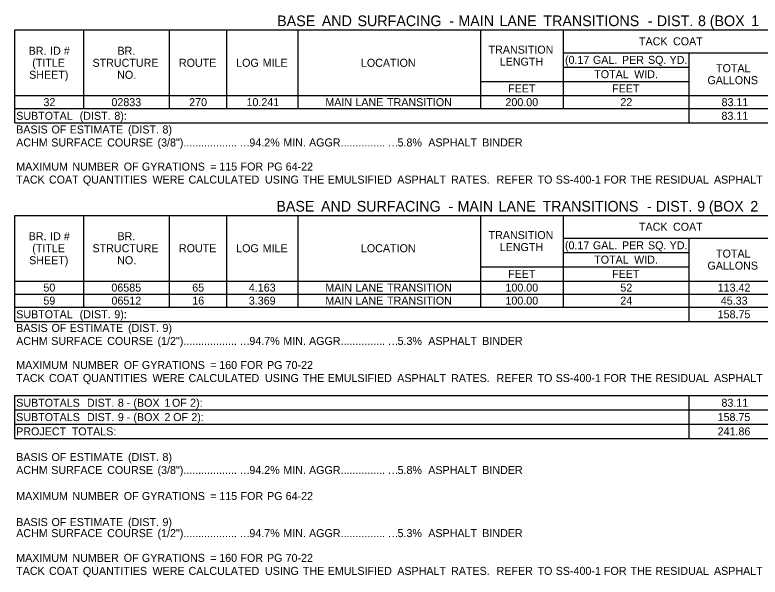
# Model space of a CAD drawing. Extents: x 544420 to 1930787, y -1947044 to 596640.
# Drawn here: x 546342 to 546901, y -1946896 to -1946475 of the extents above; entities that cross this region are included whole.
import ezdxf

# ---------------------------------------------------------------- set-up
doc = ezdxf.new("R2010")
doc.units = 0
doc.layers.add('Default', color=7, linetype='Continuous')

msp = doc.modelspace()

# ---------------------------------------------------------------- linework, layer by layer
at = {"layer": 'Default'}
for p, q in [((546342.21, -1946486.24), (547336.23, -1946486.24)), ((546342.21, -1946555.95), (546342.21, -1946486.24)), ((546342.21, -1946555.95), (546342.21, -1946486.24)), ((546393.89, -1946545.22), (546393.89, -1946486.24)), ((546458.24, -1946545.22), (546458.24, -1946486.24)), ((546501.14, -1946545.22), (546501.14, -1946486.24)), ((546554.76, -1946545.22), (546554.76, -1946486.24)), ((546691.75, -1946545.22), (546691.75, -1946486.24)), ((546753.66, -1946545.22), (546753.66, -1946486.24)), ((546753.66, -1946503.3), (546753.66, -1946486.24)), ((546753.66, -1946503.3), (547336.23, -1946503.3)), ((546847.75, -1946514.02), (546847.75, -1946503.3)), ((546847.75, -1946555.95), (546847.75, -1946503.3)), ((546753.66, -1946514.02), (546847.75, -1946514.02)), ((546691.75, -1946524.75), (546753.66, -1946524.75)), ((546691.75, -1946524.75), (546847.75, -1946524.75)), ((546847.75, -1946535.47), (546847.75, -1946524.75)), ((546342.21, -1946535.47), (546847.75, -1946535.47)), ((546342.21, -1946535.47), (547336.23, -1946535.47)), ((546847.75, -1946535.47), (546967.68, -1946535.47)), ((546342.21, -1946545.22), (547336.23, -1946545.22)), ((546342.21, -1946545.22), (547336.23, -1946545.22)), ((546342.21, -1946555.95), (547336.23, -1946555.95)), ((546342.21, -1946625.17), (547336.23, -1946625.17)), ((546342.21, -1946704.64), (546342.21, -1946625.17)), ((546342.21, -1946704.64), (546342.21, -1946625.17)), ((546393.89, -1946693.91), (546393.89, -1946625.17)), ((546458.24, -1946693.91), (546458.24, -1946625.17)), ((546501.14, -1946693.91), (546501.14, -1946625.17)), ((546554.76, -1946693.91), (546554.76, -1946625.17)), ((546691.75, -1946693.91), (546691.75, -1946625.17)), ((546753.66, -1946693.91), (546753.66, -1946625.17)), ((546753.66, -1946642.24), (546753.66, -1946625.17)), ((546753.66, -1946642.24), (547336.23, -1946642.24)), ((546847.75, -1946652.96), (546847.75, -1946642.24)), ((546847.75, -1946704.64), (546847.75, -1946642.24)), ((546753.66, -1946652.96), (546847.75, -1946652.96)), ((546691.75, -1946663.69), (546753.66, -1946663.69)), ((546691.75, -1946663.69), (546847.75, -1946663.69)), ((546847.75, -1946674.41), (546847.75, -1946663.69)), ((546342.21, -1946674.41), (547336.23, -1946674.41)), ((546847.75, -1946674.41), (546967.68, -1946674.41)), ((546342.21, -1946684.16), (547336.23, -1946684.16)), ((546342.21, -1946693.91), (547336.23, -1946693.91)), ((546342.21, -1946704.64), (547336.23, -1946704.64)), ((546342.21, -1946760.21), (546554.76, -1946760.21)), ((546342.21, -1946760.21), (547336.23, -1946760.21)), ((546342.21, -1946792.39), (546342.21, -1946760.21)), ((546342.21, -1946792.39), (546342.21, -1946760.21)), ((546554.76, -1946760.21), (547076.88, -1946760.21)), ((546847.75, -1946792.39), (546847.75, -1946760.21)), ((546342.21, -1946770.94), (547336.23, -1946770.94)), ((546342.21, -1946781.66), (547336.23, -1946781.66)), ((546342.21, -1946792.39), (547336.23, -1946792.39))]:
    msp.add_line(p, q, dxfattribs=at)

# ---------------------------------------------------------------- texts
for s, height, p in [('BASE', 8, (546538.89, -1946483.41)), (' AND', 8, (546569.4, -1946483.41)), (' SURFACING', 8, (546596.17, -1946483.41)), (' -', 8, (546665.04, -1946483.41)), (' MAIN', 8, (546671.79, -1946483.41)), (' LANE', 8, (546702.56, -1946483.41)), (' TRANSITIONS', 8, (546735.54, -1946483.41)), (' -', 8, (546813.86, -1946483.41)), (' DIST.', 8, (546820.61, -1946483.41)), (' 8', 8, (546851.51, -1946483.41)), (' (BOX', 8, (546860.33, -1946483.41)), (' 1', 8, (546891.36, -1946483.41)), ('TACK', 6, (546810.24, -1946497.77)), (' COAT', 6, (546833.52, -1946497.77)), ('BR.', 6, (546352.53, -1946504.85)), (' ID', 6, (546366.39, -1946504.85)), (' #', 6, (546376.68, -1946504.85)), ('BR.', 6, (546419.13, -1946504.85)), ('TRANSITION', 6, (546697.43, -1946503.99)), ('(TITLE', 6, (546355.22, -1946513.85)), ('STRUCTURE', 6, (546400.42, -1946513.85)), ('ROUTE', 6, (546465.22, -1946513.85)), ('LOG', 6, (546508.15, -1946513.85)), (' MILE', 6, (546525.81, -1946513.85)), ('LOCATION', 6, (546601.7, -1946513.85)), ('LENGTH', 6, (546705.8, -1946512.99)), ('(0.17', 6, (546754.73, -1946511.66)), (' GAL.', 6, (546773.46, -1946511.66)), (' PER', 6, (546795.24, -1946511.66)), (' SQ.', 6, (546814.76, -1946511.66)), (' YD.', 6, (546830.96, -1946511.66)), ('TOTAL', 6, (546868.03, -1946517.89)), ('SHEET)', 6, (546352.9, -1946522.85)), ('NO.', 6, (546418.9, -1946522.85)), ('TOTAL', 6, (546776.68, -1946522.39)), (' WID.', 6, (546804.37, -1946522.39)), ('GALLONS', 6, (546861.59, -1946526.89)), ('FEET', 6, (546712.08, -1946533.11)), ('FEET', 6, (546790.08, -1946533.11)), ('32', 6, (546363.61, -1946543.35)), ('02833', 6, (546414.6, -1946543.35)), ('270', 6, (546472.9, -1946543.35)), ('10.241', 6, (546515.91, -1946543.35)), ('MAIN', 6, (546575.02, -1946543.35)), (' LANE', 6, (546595.3, -1946543.35)), (' TRANSITION', 6, (546619.08, -1946543.35)), ('200.00', 6, (546710.09, -1946543.35)), ('22', 6, (546796.27, -1946543.35)), ('83.11', 6, (546872.16, -1946543.35)), (' (DIST.', 6, (546388.58, -1946553.59)), (' 8):', 6, (546414.55, -1946553.59)), ('SUBTOTAL', 6, (546343.19, -1946553.59)), ('83.11', 6, (546872.07, -1946553.59)), ('BASIS', 6, (546343.19, -1946563.82)), (' OF', 6, (546367.45, -1946563.82)), (' ESTIMATE', 6, (546381.04, -1946563.82)), (' (DIST.', 6, (546424.84, -1946563.82)), (' 8)', 6, (546450.65, -1946563.82)), ('ACHM', 6, (546343.19, -1946573.57)), (' SURFACE', 6, (546367.24, -1946573.57)), (' COURSE', 6, (546409.19, -1946573.57)), (' (3/8")..................', 6, (546446.94, -1946573.57)), ('94.2%', 6, (546518.04, -1946573.57)), (' MIN.', 6, (546541.28, -1946573.57)), (' AGGR...............', 6, (546560.57, -1946573.57)), ('5.8%', 6, (546629.17, -1946573.57)), ('  ASPHALT', 6, (546647.75, -1946573.57)), (' BINDER', 6, (546690.45, -1946573.57)), ('…', 6, (546510.64, -1946573.57)), ('…', 6, (546621.77, -1946573.57)), ('MAXIMUM', 6, (546343.19, -1946591.61)), (' NUMBER', 6, (546383.08, -1946591.61)), (' OF', 6, (546421.62, -1946591.61)), (' GYRATIONS', 6, (546435.21, -1946591.61)), (' 115', 6, (546493.23, -1946591.61)), (' FOR', 6, (546509.21, -1946591.61)), (' PG', 6, (546529.12, -1946591.61)), (' 64-22', 6, (546543.04, -1946591.61)), (' =', 6, (546486.48, -1946591.61)), ('TACK', 6, (546343.19, -1946601.36)), (' COAT', 6, (546365.53, -1946601.36)), (' QUANTITIES', 6, (546390.98, -1946601.36)), (' WERE', 6, (546443.18, -1946601.36)), (' CALCULATED', 6, (546470.21, -1946601.36)), (' USING', 6, (546527.53, -1946601.36)), (' THE', 6, (546555.89, -1946601.36)), (' EMULSIFIED', 6, (546574.54, -1946601.36)), (' ASPHALT', 6, (546626.73, -1946601.36)), (' RATES.', 6, (546667.09, -1946601.36)), ('  REFER', 6, (546698.97, -1946601.36)), (' TO', 6, (546731.93, -1946601.36)), (' SS-400-1', 6, (546745.53, -1946601.36)), (' FOR', 6, (546781.72, -1946601.36)), (' THE', 6, (546801.63, -1946601.36)), (' RESIDUAL', 6, (546820.28, -1946601.36)), (' ASPHALT', 6, (546864.24, -1946601.36)), ('BASE', 8, (546538.28, -1946622.35)), (' AND', 8, (546568.78, -1946622.35)), (' SURFACING', 8, (546595.55, -1946622.35)), (' MAIN', 8, (546671.17, -1946622.35)), (' LANE', 8, (546701.94, -1946622.35)), (' TRANSITIONS', 8, (546734.92, -1946622.35)), (' DIST.', 8, (546819.99, -1946622.35)), (' 9', 8, (546850.89, -1946622.35)), (' (BOX', 8, (546859.69, -1946622.35)), (' 2', 8, (546890.73, -1946622.35)), (' -', 8, (546664.43, -1946622.35)), (' -', 8, (546813.25, -1946622.35)), ('TACK', 6, (546810.24, -1946636.7)), (' COAT', 6, (546833.52, -1946636.7)), ('BR.', 6, (546352.53, -1946643.79)), (' ID', 6, (546366.39, -1946643.79)), (' #', 6, (546376.68, -1946643.79)), ('BR.', 6, (546419.13, -1946643.79)), ('TRANSITION', 6, (546697.43, -1946642.93)), ('(TITLE', 6, (546355.22, -1946652.79)), ('STRUCTURE', 6, (546400.42, -1946652.79)), ('ROUTE', 6, (546465.22, -1946652.79)), ('LOG', 6, (546508.15, -1946652.79)), (' MILE', 6, (546525.81, -1946652.79)), ('LOCATION', 6, (546601.7, -1946652.79)), ('LENGTH', 6, (546705.8, -1946651.93)), ('(0.17', 6, (546754.73, -1946650.6)), (' GAL.', 6, (546773.46, -1946650.6)), (' PER', 6, (546795.24, -1946650.6)), (' SQ.', 6, (546814.76, -1946650.6)), (' YD.', 6, (546830.96, -1946650.6)), ('TOTAL', 6, (546868.03, -1946656.82)), ('SHEET)', 6, (546352.9, -1946661.79)), ('NO.', 6, (546418.9, -1946661.79)), ('TOTAL', 6, (546776.68, -1946661.32)), (' WID.', 6, (546804.37, -1946661.32)), ('GALLONS', 6, (546861.59, -1946665.82)), ('FEET', 6, (546712.08, -1946672.05)), ('FEET', 6, (546790.08, -1946672.05)), ('50', 6, (546363.59, -1946682.29)), ('06585', 6, (546414.58, -1946682.29)), ('65', 6, (546475.2, -1946682.29)), ('4.163', 6, (546517.66, -1946682.29)), ('MAIN', 6, (546575.02, -1946682.29)), (' LANE', 6, (546595.3, -1946682.29)), (' TRANSITION', 6, (546619.08, -1946682.29)), ('100.00', 6, (546710.09, -1946682.29)), ('52', 6, (546796.27, -1946682.29)), ('113.42', 6, (546869.28, -1946682.29)), ('59', 6, (546363.58, -1946692.04)), ('06512', 6, (546414.64, -1946692.04)), ('16', 6, (546475.22, -1946692.04)), ('3.369', 6, (546517.65, -1946692.04)), ('MAIN', 6, (546575.02, -1946692.04)), (' LANE', 6, (546595.3, -1946692.04)), (' TRANSITION', 6, (546619.08, -1946692.04)), ('100.00', 6, (546710.09, -1946692.04)), ('24', 6, (546796.25, -1946692.04)), ('45.33', 6, (546871.58, -1946692.04)), ('SUBTOTAL', 6, (546343.19, -1946702.27)), (' (DIST.', 6, (546388.58, -1946702.27)), (' 9):', 6, (546414.55, -1946702.27)), ('158.75', 6, (546869.23, -1946702.27)), ('BASIS', 6, (546343.19, -1946712.51)), (' OF', 6, (546367.45, -1946712.51)), (' ESTIMATE', 6, (546381.04, -1946712.51)), (' (DIST.', 6, (546424.84, -1946712.51)), (' 9)', 6, (546450.65, -1946712.51)), ('ACHM', 6, (546343.19, -1946722.26)), (' SURFACE', 6, (546367.24, -1946722.26)), (' COURSE', 6, (546409.19, -1946722.26)), (' (1/2")..................', 6, (546446.94, -1946722.26)), ('94.7%', 6, (546518.04, -1946722.26)), (' MIN.', 6, (546541.28, -1946722.26)), (' AGGR...............', 6, (546560.57, -1946722.26)), ('5.3%', 6, (546629.17, -1946722.26)), ('  ASPHALT', 6, (546647.75, -1946722.26)), (' BINDER', 6, (546690.45, -1946722.26)), ('…', 6, (546510.64, -1946722.26)), ('…', 6, (546621.77, -1946722.26)), ('MAXIMUM', 6, (546343.19, -1946740.3)), (' NUMBER', 6, (546383.08, -1946740.3)), (' OF', 6, (546421.62, -1946740.3)), (' GYRATIONS', 6, (546435.21, -1946740.3)), (' =', 6, (546486.48, -1946740.3)), (' 160', 6, (546493.23, -1946740.3)), (' FOR', 6, (546509.14, -1946740.3)), (' PG', 6, (546529.05, -1946740.3)), (' 70-22', 6, (546542.97, -1946740.3)), ('TACK', 6, (546343.19, -1946750.05)), (' COAT', 6, (546365.53, -1946750.05)), (' QUANTITIES', 6, (546390.98, -1946750.05)), (' WERE', 6, (546443.18, -1946750.05)), (' CALCULATED', 6, (546470.21, -1946750.05)), (' USING', 6, (546527.53, -1946750.05)), (' THE', 6, (546555.89, -1946750.05)), (' EMULSIFIED', 6, (546574.54, -1946750.05)), (' ASPHALT', 6, (546626.73, -1946750.05)), (' RATES.', 6, (546667.09, -1946750.05)), ('  REFER', 6, (546698.97, -1946750.05)), (' TO', 6, (546731.93, -1946750.05)), (' SS-400-1', 6, (546745.53, -1946750.05)), (' FOR', 6, (546781.72, -1946750.05)), (' THE', 6, (546801.63, -1946750.05)), (' RESIDUAL', 6, (546820.28, -1946750.05)), (' ASPHALT', 6, (546864.24, -1946750.05)), ('SUBTOTALS', 6, (546343.19, -1946768.57)), (' DIST.', 6, (546394.02, -1946768.57)), (' 8', 6, (546417.19, -1946768.57)), (' (BOX', 6, (546428.86, -1946768.57)), (' 1', 6, (546452.14, -1946768.57)), (' OF', 6, (546457.77, -1946768.57)), (' 2):', 6, (546471.35, -1946768.57)), ('83.11', 6, (546872.07, -1946768.57)), (' -', 6, (546423.8, -1946768.57)), ('SUBTOTALS', 6, (546343.19, -1946779.3)), (' DIST.', 6, (546394.02, -1946779.3)), (' 9', 6, (546417.19, -1946779.3)), (' (BOX', 6, (546428.85, -1946779.3)), (' 2', 6, (546452.13, -1946779.3)), (' OF', 6, (546458.69, -1946779.3)), (' 2):', 6, (546472.28, -1946779.3)), ('158.75', 6, (546869.19, -1946779.3)), (' -', 6, (546423.79, -1946779.3)), ('PROJECT', 6, (546343.19, -1946790.02)), (' TOTALS:', 6, (546382.61, -1946790.02)), ('241.86', 6, (546869.21, -1946790.02)), ('BASIS', 6, (546343.19, -1946809.22)), (' OF', 6, (546367.45, -1946809.22)), (' ESTIMATE', 6, (546381.04, -1946809.22)), (' (DIST.', 6, (546424.84, -1946809.22)), (' 8)', 6, (546450.65, -1946809.22)), ('ACHM', 6, (546343.19, -1946818.97)), (' SURFACE', 6, (546367.24, -1946818.97)), (' COURSE', 6, (546409.19, -1946818.97)), (' (3/8")..................', 6, (546446.94, -1946818.97)), ('94.2%', 6, (546518.04, -1946818.97)), (' MIN.', 6, (546541.28, -1946818.97)), (' AGGR...............', 6, (546560.57, -1946818.97)), ('5.8%', 6, (546629.17, -1946818.97)), ('  ASPHALT', 6, (546647.75, -1946818.97)), (' BINDER', 6, (546690.45, -1946818.97)), ('…', 6, (546510.64, -1946818.97)), ('…', 6, (546621.77, -1946818.97)), ('MAXIMUM', 6, (546343.19, -1946838.47)), (' NUMBER', 6, (546383.08, -1946838.47)), (' OF', 6, (546421.62, -1946838.47)), (' GYRATIONS', 6, (546435.21, -1946838.47)), (' =', 6, (546486.48, -1946838.47)), (' 115', 6, (546493.23, -1946838.47)), (' FOR', 6, (546509.21, -1946838.47)), (' PG', 6, (546529.12, -1946838.47)), (' 64-22', 6, (546543.04, -1946838.47)), ('BASIS', 6, (546343.19, -1946857.97)), (' OF', 6, (546367.45, -1946857.97)), (' ESTIMATE', 6, (546381.04, -1946857.97)), (' (DIST.', 6, (546424.84, -1946857.97)), (' 9)', 6, (546450.65, -1946857.97)), ('ACHM', 6, (546343.19, -1946866.26)), (' SURFACE', 6, (546367.24, -1946866.26)), (' COURSE', 6, (546409.19, -1946866.26)), (' (1/2")..................', 6, (546446.94, -1946866.26)), ('94.7%', 6, (546518.04, -1946866.26)), (' MIN.', 6, (546541.28, -1946866.26)), (' AGGR...............', 6, (546560.57, -1946866.26)), ('5.3%', 6, (546629.17, -1946866.26)), ('  ASPHALT', 6, (546647.75, -1946866.26)), (' BINDER', 6, (546690.45, -1946866.26)), ('…', 6, (546510.64, -1946866.26)), ('…', 6, (546621.77, -1946866.26)), ('MAXIMUM', 6, (546343.19, -1946884.79)), (' NUMBER', 6, (546383.08, -1946884.79)), (' OF', 6, (546421.62, -1946884.79)), (' GYRATIONS', 6, (546435.21, -1946884.79)), (' =', 6, (546486.48, -1946884.79)), (' 160', 6, (546493.23, -1946884.79)), (' FOR', 6, (546509.14, -1946884.79)), (' PG', 6, (546529.05, -1946884.79)), (' 70-22', 6, (546542.97, -1946884.79)), ('TACK', 6, (546343.19, -1946894.54)), (' COAT', 6, (546365.53, -1946894.54)), (' QUANTITIES', 6, (546390.98, -1946894.54)), (' WERE', 6, (546443.18, -1946894.54)), (' CALCULATED', 6, (546470.21, -1946894.54)), (' USING', 6, (546527.53, -1946894.54)), (' THE', 6, (546555.89, -1946894.54)), (' EMULSIFIED', 6, (546574.54, -1946894.54)), (' ASPHALT', 6, (546626.73, -1946894.54)), (' RATES.', 6, (546667.09, -1946894.54)), ('  REFER', 6, (546698.97, -1946894.54)), (' TO', 6, (546731.93, -1946894.54)), (' SS-400-1', 6, (546745.53, -1946894.54)), (' FOR', 6, (546781.72, -1946894.54)), (' THE', 6, (546801.63, -1946894.54)), (' RESIDUAL', 6, (546820.28, -1946894.54)), (' ASPHALT', 6, (546864.24, -1946894.54))]:
    msp.add_text(s, height=height, dxfattribs=at).set_placement(p)

doc.saveas('drawing.dxf')
